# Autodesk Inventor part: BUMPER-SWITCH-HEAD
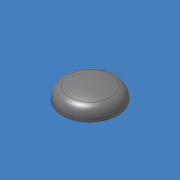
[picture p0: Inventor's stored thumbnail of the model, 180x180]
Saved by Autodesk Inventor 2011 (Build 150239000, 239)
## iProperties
Created: 2007-08
Part Number: BUMPER-SWITCH-HEAD
Material: ABS Plastic
Document SubType Name: Modeling
Density: 1.06 g/cm^3
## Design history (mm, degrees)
feature "Base1"
body "Solid1"
